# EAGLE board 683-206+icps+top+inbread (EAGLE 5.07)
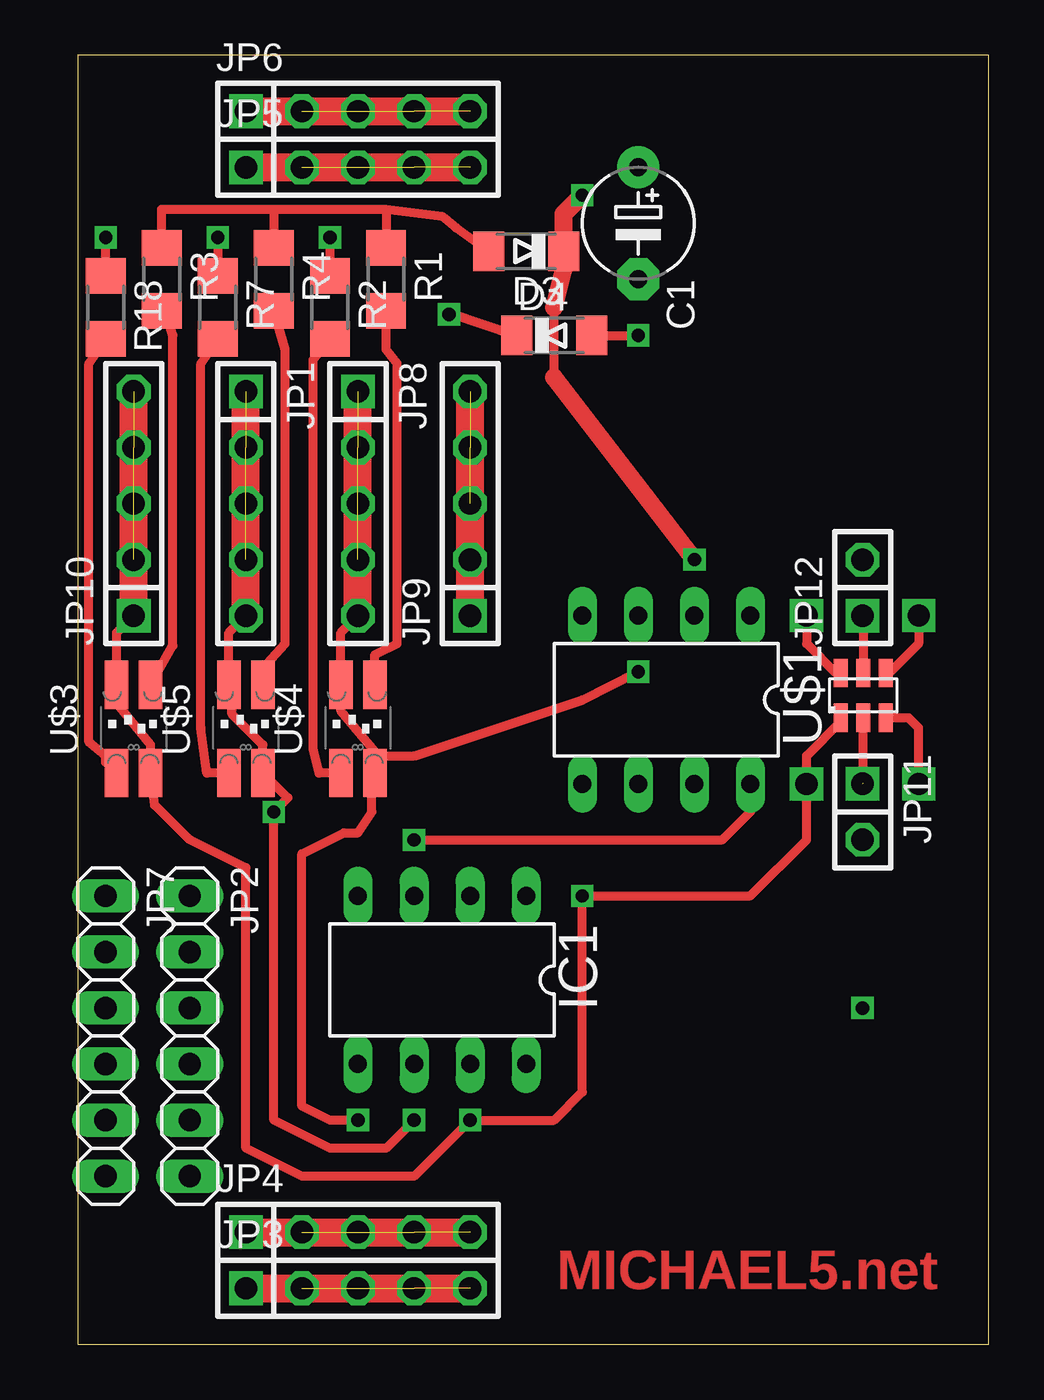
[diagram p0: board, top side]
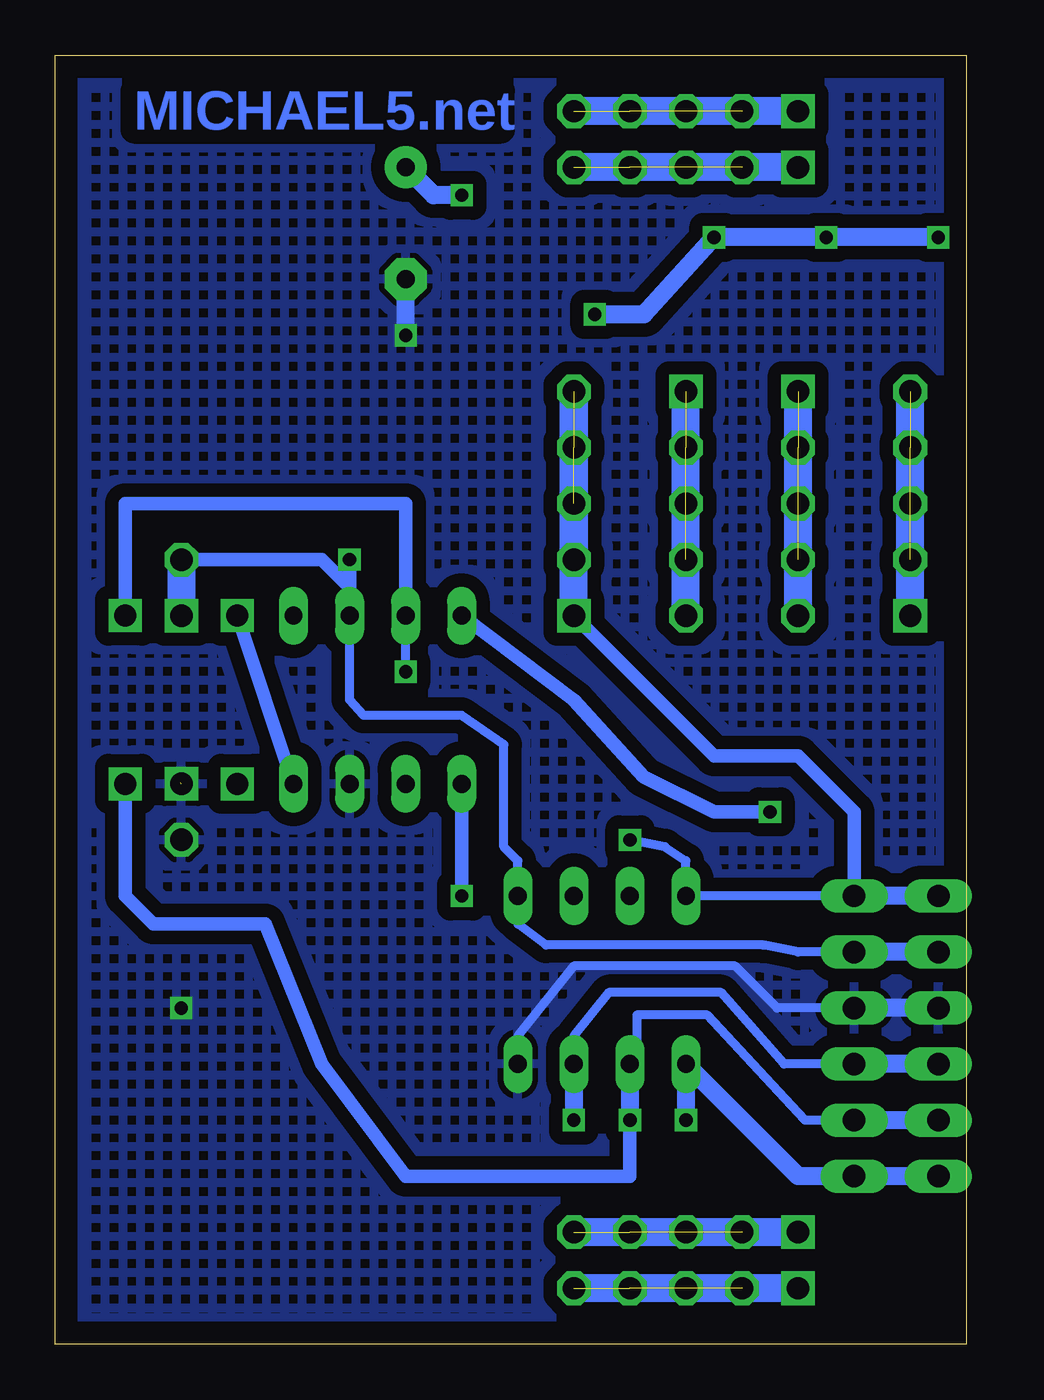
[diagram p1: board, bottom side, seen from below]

Size 41.27 x 58.42 mm. Coordinates in mm from the lower left corner, seen from the top.
Outline: 0,0 41.27,0 41.27,58.42 0,58.42 0,0
Copper layers (1*16): Top 0.035mm / dielectric 1.5mm / Bottom 0.035mm
Design rules "default": minimum track width 10mil, minimum drill 24mil, track to track 8mil, track to pad 8mil, pad to pad 8mil, via to via 8mil, smd to smd 8mil, copper to edge 40mil, drill to drill 8mil, minimum pad ring 10mil, minimum via ring 8mil, stop-mask expansion 4mil, vias tented up to drill 0mil, thermal gap 10mil
Net classes: 0 default: width 0.3 mm, drill 0.6 mm, clearance 0.2 mm; 1 power: width 0.4 mm, drill 0.6 mm, clearance 0.2 mm

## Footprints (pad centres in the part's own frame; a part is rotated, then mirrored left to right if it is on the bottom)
E5-5 = drill 0.813 pad 1.905 round: + -2.54,0 | drill 0.813 pad 1.905 octagon: - 2.54,0
MINIMELF = smd 1.4 x 1.8: A 1.7,0; C -1.7,0
DIL8 = drill 0.813 long: 1 -3.81,-3.81; 2 -1.27,-3.81; 3 1.27,-3.81; 4 3.81,-3.81; 5 3.81,3.81; 6 1.27,3.81; 7 -1.27,3.81; 8 -3.81,3.81
1X05 = drill 1.016 square: 1 -5.08,0 | drill 1.016 octagon: 2 -2.54,0; 3 0,0; 4 2.54,0; 5 5.08,0
1X06 = drill 1.016 long: 1 -6.35,0; 2 -3.81,0; 3 -1.27,0; 4 1.27,0; 5 3.81,0; 6 6.35,0
1X02 = drill 1.016 square: 1 -1.27,0 | drill 1.016 octagon: 2 1.27,0
R1206 = smd 1.6 x 1.803: 1 -1.422,0; 2 1.422,0
SOT23-6 = smd 0.635 x 1.27: 1 -1.016,-1.016; 2 0,-1.016; 3 1.016,-1.016; 4 1.016,1.016; 5 0,1.016; 6 -1.016,1.016
DUOLEDSMD = smd 1.067 x 2.184: AGRN 0.77,1.95; ARED -0.77,1.95; CGRN 0.77,-2.05; CRED -0.77,-2.05

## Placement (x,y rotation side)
C1  [E5-5]  25.4,50.8 270 top
D3  [MINIMELF]  20.32,49.53 180 top
D4  [MINIMELF]  21.59,45.72 0 top
IC1  PIC12F629P  [DIL8]  16.51,16.51 180 top
JP1  [1X05]  7.62,38.1 270 top
JP2  [1X06]  5.08,13.97 270 top
JP3  [1X05]  12.7,2.54 0 top
JP4  [1X05]  12.7,5.08 0 top
JP5  [1X05]  12.7,53.34 0 top
JP6  [1X05]  12.7,55.88 0 top
JP7  [1X06]  1.27,13.97 270 top
JP8  [1X05]  12.7,38.1 270 top
JP9  [1X05]  17.78,38.1 90 top
JP10  [1X05]  2.54,38.1 90 top
JP11  [1X02]  35.56,24.13 270 top
JP12  [1X02]  35.56,34.29 90 top
R1  [R1206]  13.97,48.26 270 top
R2  [R1206]  11.43,46.99 270 top
R3  [R1206]  3.81,48.26 270 top
R4  [R1206]  8.89,48.26 270 top
R7  [R1206]  6.35,46.99 270 top
R18  [R1206]  1.27,46.99 270 top
U$1  PIC10F206P  [DIL8]  26.67,29.21 180 top
U$2  PIC10F204OT  [SOT23-6]  35.59,29.41 0 top
U$3  DUOLEDSMD  [DUOLEDSMD]  2.54,27.94 0 top
U$4  DUOLEDSMD  [DUOLEDSMD]  12.7,27.94 0 top
U$5  DUOLEDSMD  [DUOLEDSMD]  7.62,27.94 0 top

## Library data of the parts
C1 R1-R4 R7 R18 = rcl
D3 D4 = diode
IC1 U$1 U$2 = microchip-5
JP1 JP3-JP6 JP8-JP12 = pinhead(2)
JP2 JP7 = pinhead
U$3-U$5 = led

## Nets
GP0: IC1.7 JP2.4 JP7.4 JP10.1 JP10.2 JP10.3 JP10.4 JP10.5 U$1.5 U$2.1 U$3.ARED U$3.CGRN
GP1: IC1.6 JP1.1 JP1.2 JP1.3 JP1.4 JP1.5 JP2.5 JP7.5 U$1.4 U$2.3 U$5.ARED U$5.CGRN
GP2: IC1.5 JP2.6 JP7.6 JP8.1 JP8.2 JP8.3 JP8.4 JP8.5 U$1.3 U$2.4 U$4.ARED U$4.CGRN
GP3: IC1.4 JP2.1 JP7.1 JP9.1 JP9.2 JP9.3 JP9.4 JP9.5 U$1.8 U$2.6
N$1: JP4.1 JP4.2 JP4.3 JP4.4 JP4.5
N$2: JP3.1 JP3.2 JP3.3 JP3.4 JP3.5
N$3: R3.2 U$3.AGRN
N$4: JP6.1 JP6.2 JP6.3 JP6.4 JP6.5
N$5: JP5.1 JP5.2 JP5.3 JP5.4 JP5.5
N$6: R18.2 U$3.CRED
N$7: D4.C R2.1 R7.1 R18.1
N$8: D3.A R1.1 R3.1 R4.1
N$20: R1.2 U$4.AGRN
N$23: R2.2 U$4.CRED
N$30: R4.2 U$5.AGRN
N$32: R7.2 U$5.CRED
VDD: C1.+ D3.C IC1.1 JP2.2 JP7.2 JP12.1 JP12.2 U$1.2 U$2.5
VSS: C1.- D4.A IC1.8 JP2.3 JP7.3 JP11.1 JP11.2 U$1.7 U$2.2

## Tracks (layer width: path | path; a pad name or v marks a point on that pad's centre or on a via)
GP0  (via drill 0.6, 1)  (3 unrouted)
  Top 0.406: JP10.1 1.77,32.25 U$3.ARED 1.91,29.07 1.91,28.89 3.31,27.17 U$3.CGRN 3.49,24.44 3.81,24.13 5.08,22.86 7.62,21.59 7.62,8.89 10.16,7.62 15.24,7.62 v17.78,10.16 21.59,10.16 22.86,11.43 v22.86,20.32 30.48,20.32 33.02,22.86 v33.02,25.4 33.02,26.67 34.57,28.22 U$2.1
  Top 1.27: JP10.1 JP10.5
  Bottom 0.406: JP2.4 8.26,12.7 11.11,15.94 16.19,15.94 17.78,13.97 IC1.7
  Bottom 0.61: v22.86,20.32 U$1.5
  Bottom 0.813: IC1.7 v17.78,10.16 | JP7.4 JP2.4
  Bottom 1.27: JP10.1 JP10.5
GP1  (via drill 0.6, 1)  (3 unrouted)
  Top 0.406: v15.24,10.16 13.97,8.89 11.43,8.89 8.89,10.16 v8.89,24.12 9.52,24.76 | 9.52,24.76 U$5.CGRN 8.39,27.17 6.99,28.57 6.99,28.75 U$5.ARED 6.85,32.25 JP1.5 | 9.52,24.76 v8.89,24.13 | U$2.3 37.65,28.39 38.1,27.94 v38.1,25.4
  Top 1.27: JP1.5 JP1.1
  Bottom 0.406: JP2.5 7.3,10.16 11.75,14.92 14.92,14.92 14.92,13.02 IC1.6
  Bottom 0.61: U$1.4 17.78,29.21 14.61,25.72 11.43,24.13 v8.89,24.13 | v38.1,25.4 38.1,20.32 36.83,19.05 31.75,19.05 29.21,12.7 25.4,7.62 15.24,7.62 v15.24,10.16
  Bottom 0.813: IC1.6 v15.24,10.16 | JP7.5 JP2.5
  Bottom 1.27: JP1.5 JP1.1
GP2  (via drill 0.6, 1)  (3 unrouted)
  Top 0.406: v12.7,10.16 11.43,10.16 10.16,10.79 10.16,22.23 12.06,23.18 12.7,23.18 13.34,24.13 13.34,25.75 U$4.CGRN 13.47,26.85 | v25.4,30.48 22.86,29.21 15.24,26.67 13.93,26.67 13.47,26.85 | JP8.5 11.93,32.25 U$4.ARED 11.93,28.71 13.47,26.85 | U$2.4 36.78,30.43 38.1,31.75 v38.1,33.02
  Top 1.27: JP8.5 JP8.1
  Bottom 0.406: v25.4,30.48 U$1.3
  Bottom 0.61: v38.1,33.02 38.1,38.1 25.4,38.1 U$1.3
  Bottom 0.813: v12.7,10.16 IC1.5 7.62,7.62 JP2.6 JP7.6
  Bottom 1.27: JP8.5 JP8.1
GP3  (via drill 0.6, 1)  (2 unrouted)
  Top 0.406: v15.24,22.86 29.21,22.86 30.48,24.13 U$1.8 | U$2.6 34.34,30.43 33.02,31.75 v33.02,33.02
  Top 1.27: JP9.1 JP9.5
  Bottom 0.406: JP2.1 IC1.4 12.7,21.91 13.65,22.54 v15.24,22.86
  Bottom 0.61: JP9.1 11.43,26.67 7.62,26.67 5.08,24.13 JP2.1 | U$1.8 v33.02,33.02
  Bottom 0.813: JP7.1 JP2.1
  Bottom 1.27: JP9.2 JP9.5 JP9.1
N$1  (3 unrouted)
  Top 1.27: JP4.1 JP4.5
  Bottom 1.27: JP4.1 JP4.5
N$2  (3 unrouted)
  Top 1.27: JP3.1 JP3.5
  Bottom 1.27: JP3.1 JP3.5
N$3
  Top 0.406: R3.2 3.96,46.84 4.32,45.72 4.32,31.66 U$3.AGRN
N$4  (3 unrouted)
  Top 1.27: JP6.1 JP6.5
  Bottom 1.27: JP6.1 JP6.5
N$5  (3 unrouted)
  Top 1.27: JP5.1 JP5.5
  Bottom 1.27: JP5.1 JP5.5
N$6
  Top 0.406: R18.2 0.51,44.45 0.51,27.3 1.27,26.67 1.27,26.39 U$3.CRED
N$7  (via drill 0.6)
  Top 0.406: D4.C 16.89,46.73 v16.83,46.67 | v6.35,50.16 R7.1 | R18.1 v1.27,50.16 | v11.43,50.16 R2.1
  Bottom 0.813: v16.83,46.67 14.61,46.67 v11.43,50.16 v6.35,50.16 v1.27,50.16
N$8
  Top 0.406: R3.1 3.81,51.44 8.89,51.44 | 8.89,51.44 R4.1 | 8.89,51.44 13.97,51.44 | 13.97,51.44 R1.1 | 13.97,51.44 16.51,51.12 17.14,50.59 D3.A
N$20
  Top 0.406: U$4.AGRN 13.47,31.25 14.48,31.75 14.48,44.45 13.97,45.09 R1.2
N$23
  Top 0.406: U$4.CRED 10.94,25.89 10.67,26.99 10.67,44.62 R2.2
N$30
  Top 0.406: U$5.AGRN 8.39,30.61 9.4,31.75 9.4,45.09 R4.2
N$32
  Top 0.406: U$5.CRED 5.86,25.89 5.59,27.94 5.59,44.45 R7.2
VDD  (via drill 0.6)
  Top 0.406: 21.59,43.81 21.59,46.99 | 22.02,48.69 D3.C | U$2.5 35.59,32.99 JP12.1
  Top 0.813: 21.59,46.99 22.02,48.69 | v27.94,35.56 21.59,43.81 | D3.C 22.02,51.23 v22.86,52.07
  Bottom 0.406: JP2.2 7.62,17.78 9.21,18.1 19.05,18.1 20.32,19.05 IC1.1 20.32,21.91 20.95,22.54 20.95,27.18 22.86,28.5 27.3,28.5 27.94,29.21 U$1.2 27.94,34.29
  Bottom 0.61: 27.94,34.29 29.21,35.56 JP12.2 | U$1.2 v27.94,35.56
  Bottom 0.813: v22.86,52.07 24.13,52.07 C1.+ | JP7.2 JP2.2
  Bottom 1.27: JP12.2 JP12.1
VSS  (via drill 0.6)  (1 unrouted)
  Top 0.406: D4.A v25.4,45.72 | 35.59,25.43 U$2.2
  Bottom 0.406: JP2.3 8.57,15.24 10.48,17.14 17.78,17.14 20.32,13.97 IC1.8
  Bottom 0.813: v25.4,45.72 C1.- | JP7.3 JP2.3
  other vias: 35.56,15.24
  pour Bottom (isolate 0.61, hatched): 0,58.42 40.64,58.42 40.64,0 0,0

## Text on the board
Top: MICHAEL5.net
Bottom: MICHAEL5.net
